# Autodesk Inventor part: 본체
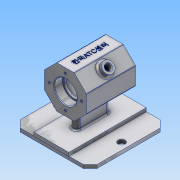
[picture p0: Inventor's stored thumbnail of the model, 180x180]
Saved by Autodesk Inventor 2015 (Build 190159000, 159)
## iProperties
Created: 2018-06
Part Number: 본체
Material: 알루미늄 6061
Document SubType Name: Modeling
Designer: SCD-A04
Density: 2.7 g/cm^3
Appearance: 알루미늄 - 평지
Mass: 551.998 g
Surface Area: 602.169 cm^2
Volume: 204.444 cm^3
Author: SCD-A04
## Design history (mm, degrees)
sketch "스케치2"
  geometry: L1 (-55, 55.234)-(55, 55.234); L2 (55, 55.234)-(55, -54.766); L3 (55, -54.766)-(-55, -54.766); L4 (-55, -54.766)-(-55, 55.234); L5 (-55, 55.234)-(55, -54.766); L6 (55, 55.234)-(-55, -54.766); 2 further points
  constraints: 12 end point, 2 midpoint, 2 parallel, 1 horizontal, 1 perpendicular
  dimensions: "d0" = 110 distance of L2.end L3.end; "d1" = 110 distance of L1.end L2.end
extrude "돌출1" new body sketch "스케치2" distance "d2" = 5; taper "d3" = 0 deg
sketch "스케치3"
  geometry: L1 (-25, 55.234)-(25, 55.234); L2 (25, 55.234)-(25, -55.234); L3 (25, -55.234)-(-25, -55.234); L4 (-25, -55.234)-(-25, 55.234); L5 (-25, 55.234)-(25, -55.234); L6 (25, 55.234)-(-25, -55.234); L7 (55, 55.234)-(-55, 55.234) reference; 2 further points
  constraints: 12 end point, 4 midpoint, 1 horizontal, 1 vertical
  dimensions: "d4" = 50 distance of L2.end L3.end; "d77" = 50 distance of L1.start L1.end
extrude "돌출2" join sketch "스케치3" distance "d6" = 5; taper "d7" = 0 deg
sketch "스케치4"
  geometry: L1 (-55, 55.234)-(-55, -54.766) reference; 2 further points
  constraints: 1 horizontal alignment
  dimensions: "d8" = 10 distance from line of point (-45, 0) L1
hole "구멍1" sketch "스케치4" at (-45, 0) diameter "d9" = 10; stored, may be unused: countersink angle "d13" = 90 deg, drill point angle "d15" = 118 deg; dims "d10" = 6, "d11" = 4, "d12" = 2, "d14" = 8
sketch "스케치5"
  geometry: L1 (0, 19)-(0, -19); L2 (-5, 19)-(-5, -19); L3 (5, -19)-(5, 19); A1 r 5 centre (0, 19) between (5, 19) and (-5, 19); A2 r 5 centre (0, -19) between (-5, -19) and (5, -19); 1 further point
  constraints: 8 end point, 4 point on circle, 4 tangent, 2 centre point, 1 midpoint, 1 parallel, 1 vertical
  dimensions: "d16" = 10 diameter of A2; "d17" = 38 distance of L1.start L1.end
extrude "돌출3" join sketch "스케치5" distance "d18" = 52; taper "d19" = 0 deg
chamfer "모따기1" distance "d20" = 10; stored, may be unused: second distance "d21" = 2, angle "d22" = 45 deg
sketch "스케치6"
  geometry: L1 (55, 0)-(50, 0) reference; L2 (50, 0)-(50, 5) reference; L3 (50, 5)-(55, 5) reference; L4 (55, 5)-(55, 0) reference; L5 (-50, 0)-(-55, 0) reference; L6 (-55, 0)-(-55, 5) reference; L7 (-55, 5)-(-50, 5) reference; L8 (-50, 5)-(-50, 0) reference; L9 (25, 10)-(25, 5) reference; L10 (25, 5)-(40, 5) reference; L11 (40, 5)-(40, 0) reference; L12 (40, 0)-(-40, 0) reference; L13 (-40, 0)-(-40, 5) reference; L14 (-40, 5)-(-25, 5) reference; L15 (-25, 5)-(-25, 10) reference; L16 (-25, 10)-(-5, 10) reference; L17 (-5, 10)-(-5, 62) reference; L18 (-5, 62)-(5, 62) reference; L19 (5, 62)-(5, 10) reference; L20 (5, 10)-(25, 10) reference; L21 (-30, 49.574)-(-30, 74.426); L22 (-30, 74.426)-(-12.426, 92); L23 (-12.426, 92)-(12.426, 92); L24 (12.426, 92)-(30, 74.426); L25 (30, 74.426)-(30, 49.574); L26 (30, 49.574)-(12.426, 32); L27 (12.426, 32)-(-12.426, 32); L28 (-12.426, 32)-(-30, 49.574); 2 further points
  constraints: 16 end point, 1 midpoint, 1 parallel, 1 vertical alignment, 17 other
  dimensions: "d23" = 30 distance from line of L28 point (0, 62)
extrude "돌출4" join sketch "스케치6" stored distance "d24" = 70; taper "d25" = 0 deg
sketch "스케치7"
  geometry: L1 (-24.853, 70)-(0, 70) reference; L2 (0, 0)-(-24.853, 0) reference; C1 r 8 at (-12.426, 35); 3 further points
  constraints: 1 centre point, 1 coincident, 1 midpoint, 1 vertical alignment
  dimensions: "d26" = 35 distance from line of L2 point (-12.426, 35); "d27" = 16 diameter of C1
extrude "돌출5" join sketch "스케치7" distance "d28" = 7; taper "d29" = 0 deg
sketch "스케치8"
  geometry: L1 (45, 0)-(-45, 0) reference; 3 further points
  constraints: 1 midpoint, 1 vertical alignment
  dimensions: "d30" = 62 distance from line of L1 point (0, 62)
hole "구멍2" sketch "스케치8" at (0, 62) diameter "d31" = 28; stored, may be unused: countersink angle "d35" = 90 deg, drill point angle "d37" = 118 deg; dims "d32" = 6, "d33" = 32, "d34" = 12, "d36" = 8
sketch "스케치9"
  geometry: L1 (-45, 0)-(45, 0) reference; C1 r 14 at (0, -62) reference; C2 r 16 at (0, -62); 2 further points
  constraints: 1 centre point, 1 coincident, 1 midpoint, 1 vertical alignment
  dimensions: "d38" = 32 diameter of C2
extrude "돌출6" cut sketch "스케치9" distance "d39" = 12; taper "d40" = 0 deg
sketch "스케치10"
  geometry: L1 (-23, 76)-(-23, 78) reference; L2 (-23, 78)-(-35, 78) reference; L3 (-35, 78)-(-35, 92) reference; L4 (-35, 92)-(35, 92) reference; L5 (35, 92)-(35, 78) reference; L6 (35, 78)-(23, 78) reference; L7 (23, 78)-(23, 76) reference; L8 (23, 76)-(-23, 76) reference; L9 (55.234, 10)-(55.234, 0) reference; L10 (55.234, 0)-(-54.766, 0) reference; L11 (-55.234, 10)-(-24, 10) reference; L12 (-24, 10)-(-24, 32) reference; L13 (-24, 32)-(-35, 32) reference; L14 (-35, 32)-(-35, 46) reference; L15 (-35, 46)-(-23, 46) reference; L16 (-23, 46)-(-23, 48) reference; L17 (-23, 48)-(23, 48) reference; L18 (23, 48)-(23, 46) reference; L19 (23, 46)-(35, 46) reference; L20 (35, 46)-(35, 32) reference; L21 (35, 32)-(24, 32) reference; L22 (24, 32)-(24, 10) reference; L23 (24, 10)-(55.234, 10) reference; L24 (20.234, 87)-(-19.766, 87); L25 (-19.766, 87)-(-19.766, 62); L26 (-19.766, 62)-(20.234, 62); L27 (20.234, 62)-(20.234, 87); L28 (20.234, 87)-(-19.766, 62); L29 (-19.766, 87)-(20.234, 62); L30 (-55.234, 5)-(-55.234, 10) reference; L31 (-54.766, 0)-(-54.766, 5) reference; L32 (-54.766, 5)-(-55.234, 5) reference; 4 further points
  constraints: 12 end point, 4 midpoint, 2 parallel, 1 horizontal, 1 perpendicular, 1 vertical alignment
  dimensions: "d41" = 62 distance between parallel lines of L10 L26; "d42" = 25 distance of L26.end L24.start; "d43" = 40 distance of L24.start L24.end
revolve "회전1" sketch "스케치10" stored, may be unused: angle "d44" = 90 deg
hole "구멍3" diameter "d47" = 8; stored, may be unused: countersink angle "d51" = 90 deg, drill point angle "d53" = 118 deg; dims "d45" = 10, "d46" = 10, "d48" = 6, "d49" = 32, "d50" = 12, "d52" = 8
sketch "스케치11"
  geometry: L1 (45, 0)-(-45, 0) reference; C1 r 16 at (0, 62) reference; 3 further points
  constraints: 1 midpoint, 1 vertical alignment
  dimensions: "d54" = 23 distance of C1.centre point (0, 85)
hole "구멍4" sketch "스케치11" at (0, 85) diameter "d55" = 3.242; stored, may be unused: countersink angle "d59" = 90 deg, drill point angle "d61" = 118 deg; dims "d56" = 8, "d57" = 32, "d58" = 12, "d60" = 10
fillet "모깎기1" dims "d65" = 1
chamfer "모따기2" distance "d66" = 1; stored, may be unused: second distance "d67" = 2, angle "d68" = 45 deg
fillet "모깎기2" dims "d69" = 0.3
fillet "모깎기3" dims "d70" = 3
fillet "모깎기4" dims "d71" = 2
fillet "모깎기5" dims "d72" = 3
sketch "스케치12"
  geometry: L1 (24.024, 0)-(0, 0) reference; L2 (42.012, 0)-(42.012, 70) reference; 2 further points
  constraints: 1 other
  dimensions: "d73" = 35 distance from line of L1 point (12.012, 35); "d74" = 30 distance from line of L2 point (12.012, 35)
feature "엠보싱1" sketch "스케치12" dims "d0" = 110, "d1" = 110, "d75" = 0.5, "d76" = 0
node "솔리드1"
mirror "대칭1"
pattern_circular "원형 패턴1" dims angle "d63" = 360 deg
mirror "대칭2"
node "절단 모서리 투영1"
node "절단 모서리 투영2"
